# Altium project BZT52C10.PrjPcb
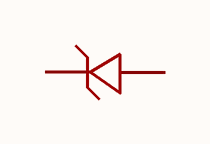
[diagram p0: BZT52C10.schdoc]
1 sheet, 1 parts. Net scope: global (net labels, ports and power ports of the same name join across sheets).

## Sheet BZT52C10.schdoc
size 127 x 101 mm

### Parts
ZD?  bzt52c10_c2103  [SOD-123_L2.8-W1.8-LS3.7-RD]  (value not drawn)

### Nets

Not connected (* = marked no-connect by the designer): ZD? 1(K) 2(A)

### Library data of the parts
ZD? = bzt52c10_c2103: 二极管配置:1个独立式;稳压值(标称值):10V;稳压值(范围):9.4V~10.6V;耗散功率(Pd):500mW;; Manufacturer: CJ(江苏长电/长晶); AddInBom: yes; ModelId: 7884390a25fb4c08947731ebfba7e3f8; ModelTransform: 144.8816,62.992,0,0,0,0,0,0,0; Diode Configuration: 1个独立式; Zener Voltage(Nom): 10V; Reverse Leakage Current (Ir): 200nA; Pd - Power Dissipation: 500mW; Impedance(Zzt): 20Ω; Impedance(Zzk): 150Ω; Operating Junction Temperature Range: -55℃~+150℃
